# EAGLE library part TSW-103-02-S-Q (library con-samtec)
THROUGH-HOLE .025" SQ POST HEADER Source: Samtec TSW.pdf
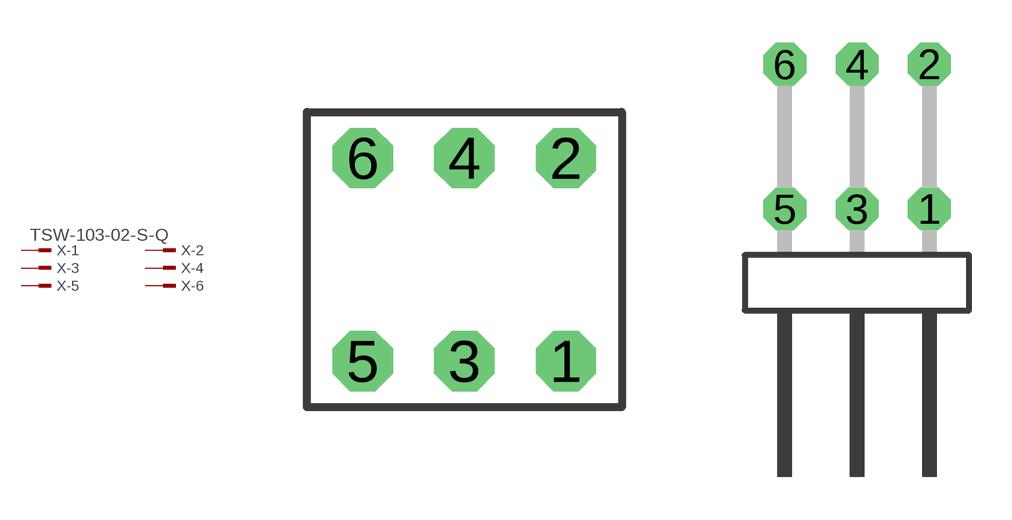
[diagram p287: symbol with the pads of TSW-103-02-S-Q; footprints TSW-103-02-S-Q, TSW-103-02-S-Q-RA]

Designator prefix X; gates -1=MPINV -2=MPIN -3=MPIN -4=MPIN -5=MPIN -6=MPIN

## TSW-103-02-S-Q (OC_FARNELL: unknown; OC_NEWARK: unknown)  [TSW-103-02-S-Q]
1  -1:1  pas
2  -2:1  pas
3  -3:1  pas
4  -4:1  pas
5  -5:1  pas
6  -6:1  pas

## TSW-103-02-S-Q-RA (OC_FARNELL: unknown; OC_NEWARK: unknown)  [TSW-103-02-S-Q-RA]
Pads as for TSW-103-02-S-Q

## Footprint TSW-103-02-S-Q (pad centres in mm)
THROUGH-HOLE .025" SQ POST HEADER Source: Samtec TSW.pdf
drill 1 pad 1.5 octagon: 1 2.54,-2.54; 2 2.54,2.54; 3 0,-2.54; 4 0,2.54; 5 -2.54,-2.54; 6 -2.54,2.54

## Footprint TSW-103-02-S-Q-RA (pad centres in mm)
THROUGH-HOLE .025" SQ POST HEADER Source: Samtec TSW.pdf
drill 1 pad 1.5 octagon: 1 2.54,1.524; 2 2.54,6.604; 3 0,1.524; 4 0,6.604; 5 -2.54,1.524; 6 -2.54,6.604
